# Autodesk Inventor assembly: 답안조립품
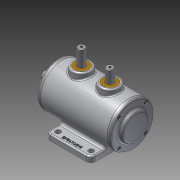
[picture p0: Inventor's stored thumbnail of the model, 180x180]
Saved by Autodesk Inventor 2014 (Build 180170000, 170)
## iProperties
Created: 2014-12
Part Number: 답안조립품
Document SubType Name: Assembly
Designer: Owner
Author: Owner
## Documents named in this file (10)
- C:\Users\Owner\Desktop\441223V1002\답안조립품.iam
- C:\Users\Owner\Desktop\441223V1002\M4-소켓머리.ipt
- C:\Users\Owner\Desktop\441223V1002\뒷커버.ipt
- C:\Users\Owner\Desktop\441223V1002\베어링 6203.ipt
- C:\Users\Owner\Desktop\441223V1002\본체.ipt
- C:\Users\Owner\Desktop\441223V1002\부시.ipt
- C:\Users\Owner\Desktop\441223V1002\슬라이더.ipt
- C:\Users\Owner\Desktop\441223V1002\앞커버.ipt
- C:\Users\Owner\Desktop\441223V1002\오일실.ipt
- C:\Users\Owner\Desktop\441223V1002\축.ipt
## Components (11 placed, 3 different names)
1. 7-베어링 6203:1
2. 8-오일실:1
3. 7-베어링 6203:2
4. 9-M4-소켓머리:1
5. 9-M4-소켓머리:3
6. 9-M4-소켓머리:4
7. 9-M4-소켓머리:5
8. 9-M4-소켓머리:2
9. 9-M4-소켓머리:6
10. 9-M4-소켓머리:7
11. 9-M4-소켓머리:8
